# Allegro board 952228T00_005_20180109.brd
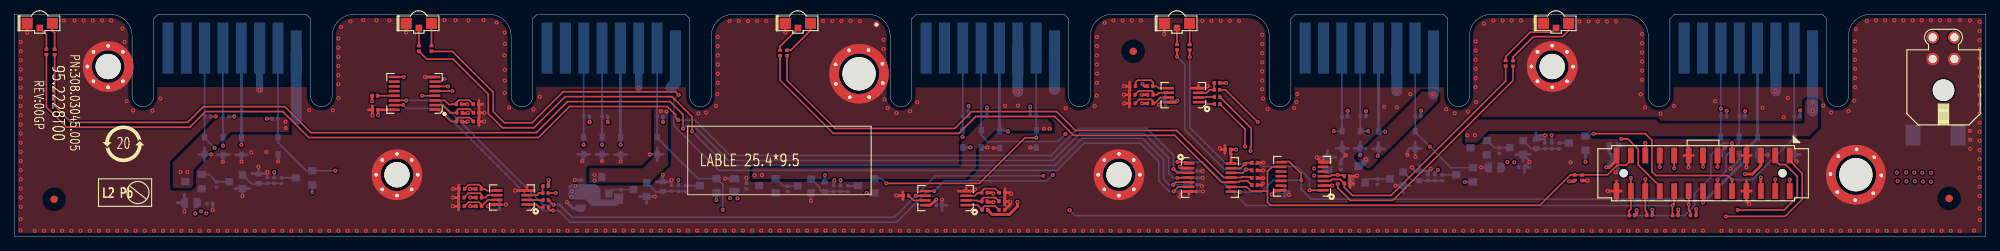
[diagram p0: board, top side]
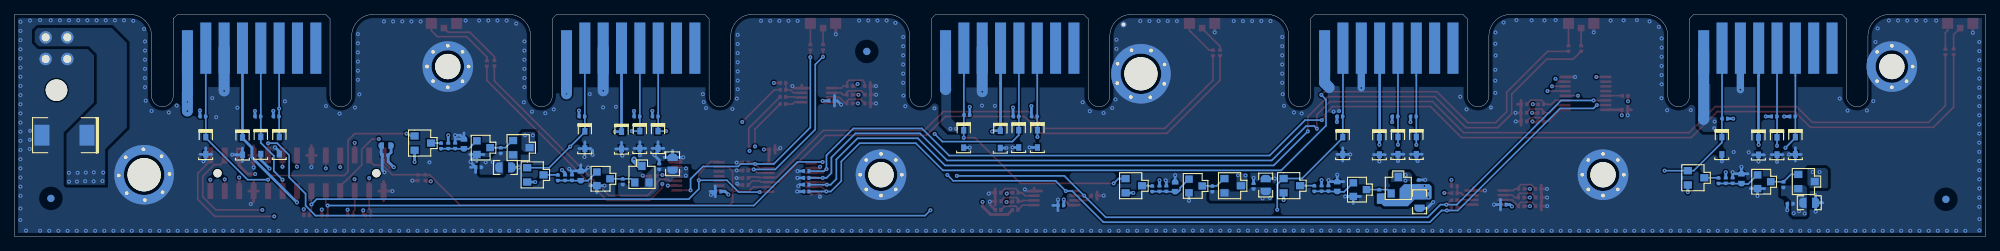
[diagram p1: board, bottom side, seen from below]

Outline 273 x 30.8 mm; copper layers: TOP, G02, T03, P04, G05, BOTTOM. Coordinates in mm from the lower left corner of the outline.
Outline path: 0,30.8 0,0 273,0 273,30.8 257.01,30.8 arc(254.89,29.92) 254.01,27.8 254.01,19.5 arc(252.51,18) 251.01,19.5 251.01,30.2 250.41,30.8 229.89,30.8 229.29,30.2 229.29,19.5 arc(227.79,18) 226.29,19.5 226.29,27.8 arc(225.41,29.92) 223.29,30.8 204.51,30.8 arc(202.39,29.92) 201.51,27.8 201.51,19.5 arc(200.01,18) 198.51,19.5 198.51,30.2 197.91,30.8 177.39,30.8 176.79,30.2 176.79,19.5 arc(175.29,18) 173.79,19.5 173.79,27.8 arc(172.91,29.92) 170.79,30.8 152.01,30.8 arc(149.89,29.92) 149.01,27.8 149.01,19.5 arc(147.51,18) 146.01,19.5 146.01,30.2 145.41,30.8 124.89,30.8 124.29,30.2 124.29,19.5 arc(122.79,18) 121.29,19.5 121.29,27.8 arc(120.41,29.92) 118.29,30.8 99.51,30.8 arc(97.39,29.92) 96.51,27.8 96.51,19.5 arc(95.01,18) 93.51,19.5 93.51,30.2 92.91,30.8 72.39,30.8 71.79,30.2 71.79,19.5 arc(70.29,18) 68.79,19.5 68.79,27.8 arc(67.91,29.92) 65.79,30.8 47.01,30.8 arc(44.89,29.92) 44.01,27.8 44.01,19.5 arc(42.51,18) 41.01,19.5 41.01,30.2 40.41,30.8 19.89,30.8 19.29,30.2 19.29,19.5 arc(17.79,18) 16.29,19.5 16.29,27.8 arc(15.41,29.92) 13.29,30.8 0,30.8

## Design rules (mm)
net group I2C: nets I2C0_HWM_SCL I2C0_HWM_SDA
net group LED_FAN: nets LED_FAN_SCL LED_FAN_SDA
net group FAN-LED-GY: nets FAN1_LED_G FAN1_LED_Y FAN2_LED_G FAN2_LED_Y FAN3_LED_G FAN3_LED_Y FAN4_LED_G FAN4_LED_Y FAN5_LED_G FAN5_LED_Y
net group FAN-PRSNT: nets FAN1_PRSNT_N FAN2_PRSNT_N FAN3_PRSNT_N FAN4_PRSNT_N FAN5_PRSNT_N
net group FAN_DIR: nets FAN1_DIR# FAN2_DIR# FAN3_DIR# FAN4_DIR# FAN5_DIR#
net group FAN_TACH: nets FAN1_TACH_IN FAN2_TACH_IN FAN3_TACH_IN FAN4_TACH_IN FAN5_TACH_IN
net group POWER: nets FAN1_PWM_CTRL FAN2_PWM_CTRL FAN3_PWM_CTRL FAN4_PWM_CTRL FAN4_PWR FAN5_PWM_CTRL

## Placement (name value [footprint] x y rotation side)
C1  10uF  [C-0805-H1_35]  24.42 4.68 270 bottom
C2  100nF  [C-0402S0]  27.06 4.56 90 bottom
C3  1uF  [C-0603S0]  33.81 8.03 180 bottom
C4  10uF  [C-0805-H1_35]  99.7 7.15 180 bottom
C5  100nF  [C-0402S0]  183.7 9.71 180 bottom
C6  1uF  [C-0603S0]  89.79 6.93 180 bottom
C7  10uF  [C-0805-H1_35]  181.85 10.09 180 bottom
C8  100nF  [C-0402S0]  101.38 7 180 bottom
C9  1uF  [C-0603S0]  112.25 6.91 180 bottom
C10  10uF  [C-0805-H1_35]  78.39 4.81 0 bottom
C11  100nF  [C-0402S0]  208.72 9.61 90 bottom
C12  1uF  [C-0603S0]  194.57 8.43 180 bottom
C13  10uF  [C-0805-H1_35]  205.01 9.59 270 bottom
C14  100nF  [C-0402S0]  78.52 7.45 180 bottom
C15  1uF  [C-0603S0]  210.75 12.85 180 bottom
C16  68uF  [C-S7_3X4_3B]  266.07 14.06 90 bottom
C17  10uF  [C-0603S0]  221.52 12.61 90 bottom
C18  100nF  [C-0402S0]  221.65 11.26 90 bottom
C19  100nF  [C-0402S0]  66.77 4.43 90 bottom
C20  100nF  [C-0402S0]  159.82 18.83 270 bottom
C21  100nF  [C-0402S0]  128.07 4.33 90 bottom
C22  100nF  [C-0402S0]  168.05 12.08 270 top
C23  1nF  [C-0402S0]  163.33 9.08 90 bottom
C24  1nF  [C-0402S0]  163.33 8.14 90 bottom
C25  1nF  [C-0402S0]  163.33 7.19 90 bottom
C26  1nF  [C-0402S0]  163.33 6.25 90 bottom
C27  1nF  [C-0402S0]  171.76 7.15 270 top
C28  1nF  [C-0402S0]  171.76 8.11 270 top
C29  1nF  [C-0402S0]  171.76 9.18 270 top
C30  1nF  [C-0402S0]  171.76 10.25 270 top
C31  100nF  [C-0402S0]  175.53 6.25 270 bottom
C32  1nF  [C-0402S0]  184.59 7.35 270 top
C33  1nF  [C-0402S0]  184.56 8.37 270 top
C34  100nF  [C-0402S0]  49.97 17.58 90 top
D1  SP4020-01FTG  [SOD-323H1_1]  31.45 12.54 0 bottom
D2  SP4020-01FTG  [SOD-323H1_1]  36.52 12.59 0 bottom
D3  SP4020-01FTG  [SOD-323H1_1]  28.88 12.56 0 bottom
D4  SP4020-01FTG  [SOD-323H1_1]  83.95 12.56 0 bottom
D5  SP4020-01FTG  [SOD-323H1_1]  89.03 12.59 0 bottom
D6  SP4020-01FTG  [SOD-323H1_1]  81.38 12.61 0 bottom
D7  SP4020-01FTG  [SOD-323H1_1]  136.45 13.48 0 bottom
D8  SP4020-01FTG  [SOD-323H1_1]  141.53 13.53 0 bottom
D9  SP4020-01FTG  [SOD-323H1_1]  133.91 13.55 0 bottom
D10  SP4020-01FTG  [SOD-323H1_1]  188.92 13.35 0 bottom
D11  SP4020-01FTG  [SOD-323H1_1]  194 13.4 0 bottom
D12  SP4020-01FTG  [SOD-323H1_1]  186.38 13.43 0 bottom
D13  SP4020-01FTG  [SOD-323H1_1]  241.42 12.54 0 bottom
D14  SP4020-01FTG  [SOD-323H1_1]  246.5 12.59 0 bottom
D15  SP4020-01FTG  [SOD-323H1_1]  238.88 12.63 0 bottom
D16  SP4020-01FTG  [SOD-323H1_1]  26.34 12.59 0 bottom
D17  SP4020-01FTG  [SOD-323H1_1]  78.84 12.61 0 bottom
D18  SP4020-01FTG  [SOD-323H1_1]  131.32 13.55 0 bottom
D19  SP4020-01FTG  [SOD-323H1_1]  183.87 13.43 0 bottom
D20  SP4020-01FTG  [SOD-323H1_1]  236.32 12.61 0 bottom
D21  12-22A/Y2G6C-B30/2C  [LD-12-22H1S1]  3.51 29.56 270 top
D22  12-22A/Y2G6C-B30/2C  [LD-12-22H1S1]  56.01 29.56 270 top
D23  12-22A/Y2G6C-B30/2C  [LD-12-22H1S1]  108.51 29.56 270 top
D24  12-22A/Y2G6C-B30/2C  [LD-12-22H1S1]  161.01 29.56 270 top
D25  12-22A/Y2G6C-B30/2C  [LD-12-22H1S1]  213.51 29.56 270 top
FD*  -  [unnamed#2]  5.49 5.17 0 top
FD*#2  -  [unnamed#2]  154.95 25.69 0 top
FD*#3  -  [unnamed#2]  267.95 5.29 0 top
FD*#4  -  [unnamed#2]  154.95 25.66 180 bottom
FD*#5  -  [unnamed#2]  5.49 5.17 180 bottom
FD*#6  -  [unnamed#2]  267.95 5.29 180 bottom
H1  Hole-3.5/7.0mm  [GMTH138R276]  212.98 23.57 0 top
H2  Hole-4.6/8.0mm  [GMTH181R325S0]  255.04 8.57 0 top
H3  Hole-3.5/7.0mm  [GMTH138R276]  52.98 8.57 0 top
H4  Hole-3.5/7.0mm  [GMTH138R276]  152.98 8.57 0 top
H5  Hole-4.6/8.0mm  [GMTH181R325S0]  116.98 22.57 25 top
H6  Hole-3.5/7.0mm  [GMTH138R276#2]  12.98 23.57 0 top
J1  FAN CONN  [CN-S8X1-2_54-FPC]  30.15 24.82 90 bottom
J2  FAN CONN  [CN-S8X1-2_54-FPC]  82.65 24.82 90 bottom
J3  FAN CONN  [CN-S8X1-2_54-FPC]  135.15 24.82 90 bottom
J4  FAN CONN  [CN-S8X1-2_54-FPC]  187.65 24.82 90 bottom
J5  FAN CONN  [CN-S8X1-2_54-FPC]  240.15 24.82 90 bottom
J6  HS5513V-R  [CN-S13X2-2HD]  233.87 8.78 90 top
J7  HM4002E-LH  [CN-D2X2-3BRTS0]  267.18 20.69 0 top
NOREF  -  []  15.1 12.86 0 top
NOREF#2  -  []  -72.65 -339.14 0 top
NOREF#3  -  []  0 30.8 0 top
NOREF#4  -  []  151.85 -209.5 0 top
NOREF#5  -  []  11.39 4.2 0 top
NOREF#6  -  []  0 0 90 top
NOREF#7  -  []  -208.37 -462.07 0 top
Q1  AP2323GN-HF  [SOT-23D]  24.8 7.63 0 bottom
Q2  AP2323GN-HF  [SOT-23D]  40.1 8.15 0 bottom
Q3  AP2323GN-HF  [SOT-23D]  81.34 7.12 270 bottom
Q4  AP2323GN-HF  [SOT-23D]  96.08 7.06 0 bottom
Q5  AP2323GN-HF  [SOT-23D]  104.27 7.05 0 bottom
Q6  AP2323GN-HF  [SOT-23D]  117.97 7.05 0 bottom
Q7  AP2323GN-HF  [SOT-23D]  186.09 8.65 270 bottom
Q8  AP2323GN-HF  [SOT-23D]  200.85 8.55 0 bottom
Q9  AP2323GN-HF  [SOT-23D]  202.8 12.33 0 bottom
Q10  AP2323GN-HF  [SOT-23D]  216.44 12.96 0 bottom
R1  10Kohm  [R-0402S0]  28 7.2 180 bottom
R2  10Kohm  [R-0402S0]  35.98 7.77 0 bottom
R3  10Kohm  [R-0402S0]  36.98 7.75 180 bottom
R4  100Kohm  [R-0402S0]  35.03 7.77 180 bottom
R5  1Kohm  [R-0402S0]  36.1 16.35 270 bottom
R6  1Kohm  [R-0402S0]  29.29 16.65 90 bottom
R7  10Kohm  [R-0402S0]  83.98 6.11 180 bottom
R8  10Kohm  [R-0402S0]  91.96 6.68 0 bottom
R9  10Kohm  [R-0402S0]  92.97 6.65 180 bottom
R10  100Kohm  [R-0402S0]  91.01 6.68 180 bottom
R11  1Kohm  [R-0402S0]  89.43 16.65 90 bottom
R12  1Kohm  [R-0402S0]  81.79 16.65 90 bottom
R13  10Kohm  [R-0402S0]  107.09 6.61 180 bottom
R14  10Kohm  [R-0402S0]  114.41 6.65 0 bottom
R15  10Kohm  [R-0402S0]  115.42 6.63 180 bottom
R16  100Kohm  [R-0402S0]  113.46 6.65 180 bottom
R17  1Kohm  [R-0402S0]  141.1 16.87 270 bottom
R18  1Kohm  [R-0402S0]  134.29 16.65 90 bottom
R19  10Kohm  [R-0402S0]  188.76 7.6 180 bottom
R20  10Kohm  [R-0402S0]  196.74 8.17 0 bottom
R21  10Kohm  [R-0402S0]  197.74 8.15 180 bottom
R22  100Kohm  [R-0402S0]  195.79 8.18 180 bottom
R23  1Kohm  [R-0402S0]  194.41 16.65 90 bottom
R24  1Kohm  [R-0402S0]  186.79 16.65 90 bottom
R25  10Kohm  [R-0402S0]  205.65 11.92 180 bottom
R26  10Kohm  [R-0402S0]  212.92 12.59 0 bottom
R27  10Kohm  [R-0402S0]  213.92 12.57 180 bottom
R28  100Kohm  [R-0402S0]  211.97 12.6 180 bottom
R29  1Kohm  [R-0402S0]  246.91 16.65 90 bottom
R30  1Kohm  [R-0402S0]  239.29 16.65 90 bottom
R31  4.7K  [R-0402S0]  73.57 7 270 top
R32  4.7K  [R-0402S0]  64.31 4.22 270 top
R33  0ohm  [R-0402S0]  73.56 6.02 270 top
R34  4.7K  [R-0402S0]  64.31 5.41 270 top
R35  4.7K  [R-0402S0]  64.28 6.61 270 top
R36  0ohm  [R-0402S0]  73.58 4.05 90 top
R37  4.7K  [R-0402S0]  61.92 4.22 270 top
R38  4.7K  [R-0402S0]  61.9 5.41 270 top
R39  0ohm  [R-0402S0]  73.58 5.04 90 top
R40  4.7K  [R-0402S0]  61.95 6.61 270 top
R41  4.7Kohm  [R-0402S0]  226.45 2.96 90 top
R42  4.7Kohm  [R-0402S0]  224.04 2.93 90 top
R43  4.7K  [R-0402S0]  166.56 21.3 270 top
R44  4.7K  [R-0402S0]  157.33 18.47 270 top
R45  4.7K  [R-0402S0]  157.33 19.66 270 top
R46  4.7K  [R-0402S0]  157.3 20.86 270 top
R47  0ohm  [R-0402S0]  166.55 20.35 270 top
R48  0ohm  [R-0402S0]  166.57 18.38 90 top
R49  4.7K  [R-0402S0]  154.84 18.47 270 top
R50  4.7K  [R-0402S0]  154.81 19.66 270 top
R51  0ohm  [R-0402S0]  166.57 19.37 90 top
R52  4.7K  [R-0402S0]  154.86 20.86 270 top
R53  4.7Kohm  [R-0402S0]  134.35 6.08 90 top
R54  4.7Kohm  [R-0402S0]  134.36 4.89 90 top
R55  4.7Kohm  [R-0402S0]  134.41 3.69 90 top
R56  4.7Kohm  [R-0402S0]  136.78 6.09 270 top
R57  4.7Kohm  [R-0402S0]  136.75 4.89 270 top
R58  4.7Kohm  [R-0402S0]  136.75 3.69 270 top
R59  200ohm  [R-0402S0]  123.46 5.68 90 top
R60  4.7Kohm  [R-0402S0]  232.52 2.96 90 top
R61  4.7Kohm  [R-0402S0]  230.03 2.93 90 top
R62  4.7Kohm  [R-0402S0]  216.09 8.16 0 top
R63  4.7Kohm  [R-0402S0]  217.13 8.16 180 top
R64  4.7Kohm  [R-0402S0]  49.93 19.53 270 top
R65  4.7Kohm  [R-0402S0]  61.61 15.97 90 top
R66  4.7Kohm  [R-0402S0]  61.64 17.16 90 top
R67  4.7Kohm  [R-0402S0]  61.56 18.35 90 top
R68  4.7Kohm  [R-0402S0]  63.93 15.96 270 top
R69  4.7Kohm  [R-0402S0]  63.95 17.16 270 top
R70  150ohm  [R-0402S0]  4.42 25.62 180 top
R71  150ohm  [R-0402S0]  5.57 25.6 180 top
R72  150ohm  [R-0402S0]  56.01 26.08 180 top
R73  150ohm  [R-0402S0]  57.76 26.08 180 top
R74  150ohm  [R-0402S0]  106.02 25.47 180 top
R75  150ohm  [R-0402S0]  107.01 25.45 180 top
R76  150ohm  [R-0402S0]  161.01 26.26 180 top
R77  150ohm  [R-0402S0]  162.76 26.24 180 top
R78  150ohm  [R-0402S0]  206.53 24.03 180 top
R79  150ohm  [R-0402S0]  207.57 24.01 180 top
R80  4.7Kohm  [R-0402S0]  63.93 18.35 270 top
R81  1Kohm  [R-0402S0]  26.74 16.65 90 bottom
R82  1Kohm  [R-0402S0]  79.25 16.65 90 bottom
R83  1Kohm  [R-0402S0]  131.74 16.65 90 bottom
R84  1Kohm  [R-0402S0]  184.24 16.65 90 bottom
R85  1Kohm  [R-0402S0]  236.74 16.65 90 bottom
U1  2N7002  [SOT-23BH1_11]  30.67 7.6 0 bottom
U2  2N7002  [SOT-23BH1_11]  86.65 6.51 0 bottom
U3  2N7002  [SOT-23BH1_11]  109.41 7.02 0 bottom
U4  2N7002  [SOT-23BH1_11]  191.42 8.01 0 bottom
U5  2N7002  [SOT-23BH1_11]  208.03 12.33 0 bottom
U6  TMP75AIDGKR  [MSOP-8]  68.9 5.41 0 top
U7  TMP75AIDGKR  [MSOP-8]  161.89 19.61 0 top
U8  M24128-BRDW6TP  [MSOP-8A]  128.96 5.34 0 top
U9  MC74HC164ADTR2G  [SSOP-14S0]  165.59 8.19 180 top
U10  MC74HC164ADTR2G  [SSOP-14S0]  178.34 8.37 0 top
U11  TCA9554PWR  [SSOP-16C]  55.41 19.85 0 top

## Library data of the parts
C1-C15 C17-C34 = CAP
C16 = CAP-TAN
D1-D20 = DIODE ZENER
D21-D25 = LED-YG-3
H1-H6 = Hole-MTG-8VIA
J1-J5 = FAN CONN_3
J6 = CON13X2
J7 = CON2X2
Q1-Q10 = PFET-3P-GSD
R1-R85 = RES
U1-U5 = NFET-3P-GSD
U6 U7 = ADT75ARZ
U8 = M24C02
U9 U10 = SN74HC164D_0
U11 = PCA9557PW_1

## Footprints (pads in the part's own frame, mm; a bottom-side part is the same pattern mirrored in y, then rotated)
C-0402S0
  custom 0.127x0.127 smd: 1(0,-0.406) 2(0,0.406)
C-0603S0
  custom 0.191x0.191 smd: 1(0,-0.686) 2(0,0.686)
C-0805-H1_35
  custom 0.254x0.254 smd: 1(0,-0.889) 2(0,0.889)
C-S7_3X4_3B
  rect 2.896x2.083 smd: 1(0,-3.123) 2(0,3.123)
CN-D2X2-3BRTS0
  round 2.997 hole 2.997 unplated: (0,-0.391)
  round 1.727 hole 1.118: 1(1.501,3.929) 2(-1.499,3.929) 3(1.501,6.929) 4(-1.499,6.929)
CN-S8X1-2_54-FPC
  rect 6.045x1.524 smd: 1(0.77,8.89)
  rect 7.112x1.524 smd: 2(1.306,6.35) 3(1.306,3.81) 4(1.306,1.27) 5(1.306,-1.27) 6(1.306,-3.81) 7(1.306,-6.35) 8(1.306,-8.89)
CN-S13X2-2HD
  round 1.143 hole 1.143 unplated: (0,11.001) (0,-11.001)
  rect 2.184x0.813 smd: 1(2.471,-11.999) 2(-2.471,-11.999) 3(2.471,-10) 4(-2.471,-10) 5(2.471,-8.001) 6(-2.471,-8.001) 7(2.471,-5.999) 8(-2.471,-5.999) 9(2.471,-4) 10(-2.471,-4) 11(2.471,-1.999) 12(-2.471,-1.999) 13(2.471,0) 14(-2.471,0) 15(2.471,1.999) 16(-2.471,1.999) 17(2.471,4) 18(-2.471,4) 19(2.471,5.999) 20(-2.471,5.999) 21(2.471,8.001) 22(-2.471,8.001) 23(2.471,10) 24(-2.471,10) 25(2.471,11.999) 26(-2.471,11.999)
GMTH138R276
  round 3.505 hole 3.505 unplated: (0,0)
  round 0.813 hole 0.508: 1(2.883,0) 2(2.039,2.039) 3(0,2.883) 4(-2.039,2.039) 5(-2.883,0) 6(-2.039,-2.039) 7(0,-2.883) 8(2.039,-2.039)
GMTH138R276#2
  round 3.505 hole 3.505 unplated: (0,0)
  round 0.813 hole 0.508: 1(106.41,5.829) 2(2.039,2.039) 3(0,2.883) 4(-2.039,2.039) 5(-2.883,0) 6(-2.039,-2.039) 7(0,-2.883) 8(2.039,-2.039)
GMTH181R325S0
  round 4.597 hole 4.597 unplated: (0,0)
  round 0.813 hole 0.508: 1(0.102,3.516) 2(-2.415,2.558) 3(-3.516,0.102) 4(-2.558,-2.415) 5(-0.102,-3.516) 6(2.415,-2.558) 7(3.516,-0.102) 8(2.558,2.415)
LD-12-22H1S1
  rect 0.914x0.914 smd: 1(0.65,0)
  rect 1.524x1.524 smd: 2(0,1.75) 3(0,-1.75)
MSOP-8
  rect 1.524x0.356 smd: 1(2.07,-0.975) 2(2.07,-0.325) 3(2.07,0.325) 4(2.07,0.975) 5(-2.07,0.975) 6(-2.07,0.325) 7(-2.07,-0.325) 8(-2.07,-0.975)
MSOP-8A
  rect 1.524x0.356 smd: 1(2.819,-0.975) 2(2.819,-0.325) 3(2.819,0.325) 4(2.819,0.975) 5(-2.819,0.975) 6(-2.819,0.325) 7(-2.819,-0.325) 8(-2.819,-0.975)
R-0402S0
  custom 0.127x0.127 smd: 1(0,-0.406) 2(0,0.406)
SOD-323H1_1
  rect 0.711x0.914 smd: 1(0,1.199) 2(0,-1.199)
SOT-23BH1_11
  rect 1.067x1.016 smd: 1(0.919,-0.95) 2(0.919,0.95) 3(-0.919,0)
SOT-23D
  rect 1.143x1.016 smd: 1(1.143,-0.991) 2(1.143,0.991) 3(-1.143,0)
SSOP-14S0
  rect 1.524x0.356 smd: 1(2.918,-1.951) 2(2.918,-1.3) 3(2.918,-0.65) 4(2.918,0) 5(2.918,0.65) 6(2.918,1.3) 7(2.918,1.951) 8(-2.918,1.951) 9(-2.918,1.3) 10(-2.918,0.65) 11(-2.918,0) 12(-2.918,-0.65) 13(-2.918,-1.3) 14(-2.918,-1.951)
SSOP-16C
  rect 1.524x0.356 smd: 1(2.819,-2.276) 2(2.819,-1.626) 3(2.819,-0.975) 4(2.819,-0.325) 5(2.819,0.325) 6(2.819,0.975) 7(2.819,1.626) 8(2.819,2.276) 9(-2.819,2.276) 10(-2.819,1.626) 11(-2.819,0.975) 12(-2.819,0.325) 13(-2.819,-0.325) 14(-2.819,-0.975) 15(-2.819,-1.626) 16(-2.819,-2.276)
unnamed#2
  round 1.016 smd: 1(0,0)

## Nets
FAN1_DIR#: D16.2(C) J1.6(GND_INLET) R81.1 U11.4(P0)
FAN1_LED_G: C24.1 R71.2 U9.4(QB)
FAN1_LED_Y: C23.1 R70.2 U9.3(QA)
FAN1_PRSNT_N: D2.2(C) J1.2(PRSNT_N) J6.1 Q2.1(G) R5.1
FAN1_PWM_CTRL: D1.2(C) J1.4(PWM_OUTLET) J6.5
FAN1_PWR: J1.1(P12V) Q1.3(D)
FAN1_PWR_ON: C3.1 R2.2 R3.1 R4.1 U1.1(G)
FAN1_TACH_IN: D3.2(C) J1.5(TACH_OUTLET) J6.3 R6.1
FAN2_DIR#: D17.2(C) J2.6(GND_INLET) R82.1 U11.5(P1)
FAN2_LED_G: C26.1 R73.2 U9.6(QD)
FAN2_LED_Y: C25.1 R72.2 U9.5(QC)
FAN2_PRSNT_N: D5.2(C) J2.2(PRSNT_N) J6.9 Q4.1(G) R11.1
FAN2_PWM_CTRL: D4.2(C) J2.4(PWM_OUTLET) J6.13
FAN2_PWR: J2.1(P12V) Q3.3(D)
FAN2_PWR_ON: C6.1 R8.2 R9.1 R10.1 U2.1(G)
FAN2_TACH_IN: D6.2(C) J2.5(TACH_OUTLET) J6.11 R12.1
FAN3_DIR#: D18.2(C) J3.6(GND_INLET) R83.1 U11.6(P2)
FAN3_LED_G: C28.1 R75.2 U9.11(QF)
FAN3_LED_Y: C27.1 R74.2 U9.10(QE)
FAN3_PRSNT_N: D8.2(C) J3.2(PRSNT_N) J6.17 Q6.1(G) R17.1
FAN3_PWM_CTRL: D7.2(C) J3.4(PWM_OUTLET) J6.21
FAN3_PWR: J3.1(P12V) Q5.3(D)
FAN3_PWR_ON: C9.1 R14.2 R15.1 R16.1 U3.1(G)
FAN3_TACH_IN: D9.2(C) J3.5(TACH_OUTLET) J6.19 R18.1
FAN4_DIR#: D19.2(C) J4.6(GND_INLET) R84.1 U11.7(P3)
FAN4_LED_G: C30.1 R77.2 U9.13(QH) U10.1(A)
FAN4_LED_Y: C29.1 R76.2 U9.12(QG)
FAN4_PRSNT_N: D11.2(C) J4.2(PRSNT_N) J6.2 Q8.1(G) R23.1
FAN4_PWM_CTRL: D10.2(C) J4.4(PWM_OUTLET) J6.6
FAN4_PWR: J4.1(P12V) Q7.3(D)
FAN4_PWR_ON: C12.1 R20.2 R21.1 R22.1 U4.1(G)
FAN4_TACH_IN: D12.2(C) J4.5(TACH_OUTLET) J6.4 R24.1
FAN5_DIR#: D20.2(C) J5.6(GND_INLET) R85.1 U11.9(P4)
FAN5_LED_G: C33.1 R79.2 U10.4(QB)
FAN5_LED_Y: C32.1 R78.2 U10.3(QA)
FAN5_PRSNT_N: D14.2(C) J5.2(PRSNT_N) J6.10 Q10.1(G) R29.1
FAN5_PWM_CTRL: D13.2(C) J5.4(PWM_OUTLET) J6.14
FAN5_PWR: J5.1(P12V) Q9.3(D)
FAN5_PWR_ON: C15.1 R26.2 R27.1 R28.1 U5.1(G)
FAN5_TACH_IN: D15.2(C) J5.5(TACH_OUTLET) J6.12 R30.1
FAN_GND: C1.2 C2.2 C3.2 C4.2 C5.2 C6.2 C7.2 C8.2 C9.2 C10.2 C11.2 C12.2 C13.2 C14.2 C15.2 C16.2 C17.2 C18.2 C19.2 C20.2 C21.2 C22.1 C23.2 C24.2 C25.2 C26.2 C27.2 C28.2 C29.2 C30.2 C31.1 C32.2 C33.2 C34.2 D1.1(A) D2.1(A) D3.1(A) D4.1(A) D5.1(A) D6.1(A) D7.1(A) D8.1(A) D9.1(A) D10.1(A) D11.1(A) D12.1(A) D13.1(A) D14.1(A) D15.1(A) D16.1(A) D17.1(A) D18.1(A) D19.1(A) D20.1(A) D21.3 D22.3 D23.3 D24.3 D25.3 H1.1(GND1) H1.2(GND2) H1.3(GND3) H1.4(GND4) H1.5(GND5) H1.6(GND6) H1.7(GND7) H1.8(GND8) H2.1(GND1) H2.2(GND2) H2.3(GND3) H2.4(GND4) H2.5(GND5) H2.6(GND6) H2.7(GND7) H2.8(GND8) H3.1(GND1) H3.2(GND2) H3.3(GND3) H3.4(GND4) H3.5(GND5) H3.6(GND6) H3.7(GND7) H3.8(GND8) H4.1(GND1) H4.2(GND2) H4.3(GND3) H4.4(GND4) H4.5(GND5) H4.6(GND6) H4.7(GND7) H4.8(GND8) H5.1(GND1) H5.2(GND2) H5.3(GND3) H5.4(GND4) H5.5(GND5) H5.6(GND6) H5.7(GND7) H5.8(GND8) H6.1(GND1) H6.2(GND2) H6.3(GND3) H6.4(GND4) H6.5(GND5) H6.6(GND6) H6.7(GND7) H6.8(GND8) J1.3(GND_OUTLET) J2.3(GND_OUTLET) J3.3(GND_OUTLET) J4.3(GND_OUTLET) J5.3(GND_OUTLET) J6.7 J6.8 J6.15 J6.26 J7.1 J7.2 R4.2 R10.2 R16.2 R22.2 R28.2 R37.1 R38.1 R40.1 R49.1 R50.1 R52.1 R56.2 R57.2 R58.2 R59.2 R63.2 R68.2 R69.2 R80.2 U1.2(S) U2.2(S) U3.2(S) U4.2(S) U5.2(S) U6.4(GND) U7.4(GND) U8.4(VSS) U9.7(GND) U10.7(GND) U11.8(GND)
FAN_P3V3: C17.1 C18.1 C19.1 C20.1 C21.1 C22.2 C31.2 C34.1 J6.25 Q2.2(S) Q4.2(S) Q6.2(S) Q8.2(S) Q10.2(S) R2.1 R5.2 R6.2 R8.1 R11.2 R12.2 R14.1 R17.2 R18.2 R20.1 R23.2 R24.2 R26.1 R29.2 R30.2 R31.2 R32.1 R34.1 R35.1 R41.1 R42.1 R43.2 R44.1 R45.1 R46.1 R53.1 R54.1 R55.1 R60.1 R61.1 R62.1 R64.1 R65.1 R66.1 R67.1 R81.2 R82.2 R83.2 R84.2 R85.2 U6.8(VDD) U7.8(VDD) U8.8(VCC) U9.2(B) U9.14(VCC) U10.2(B) U10.14(VCC) U11.16(VCC)
FAN_P12V: C1.1 C2.1 C4.1 C5.1 C7.1 C8.1 C10.1 C11.1 C13.1 C14.1 C16.1 J7.3 J7.4 Q1.2(S) Q3.2(S) Q5.2(S) Q7.2(S) Q9.2(S) R1.1 R7.1 R13.1 R19.1 R25.1
I2C0_HWM_SCL: J6.22 R39.1 R41.2 R51.1 U8.6(SCL) U11.14(SCL)
I2C0_HWM_SDA: J6.24 R36.1 R42.2 R48.1 U8.5(SDA) U11.15(SDA)
LED_FAN_CLR_N: J6.23 R62.2 R63.1 U9.9(CLR#) U10.9(CLR#)
LED_FAN_SCL: J6.16 R60.2 U9.8(CLK) U10.8(CLK)
LED_FAN_SDA: J6.18 R61.2 U9.1(A)
TEMP_ALERT: J6.20 R33.2 R47.2
N02942: Q1.1(G) R1.2 U1.3(D)
N03390: Q2.3(D) R3.2
N11321: Q3.1(G) R7.2 U2.3(D)
N11737: Q4.3(D) R9.2
N13765: Q5.1(G) R13.2 U3.3(D)
N14181: Q6.3(D) R15.2
N14871: Q8.3(D) R21.2
N17617712: Q7.1(G) R19.2 U4.3(D)
N32077972: R34.2 R38.2 U6.6(A1)
N32077983: R32.2 R37.2 U6.7(A0)
N32078033: R35.2 R40.2 U6.5(A2)
N32081443: R31.1 R33.1 U6.3(OS/ALERT)
N32081820: R44.2 R49.2 U7.7(A0)
N32081822: R45.2 R50.2 U7.6(A1)
N32081881: R46.2 R52.2 U7.5(A2)
N32081935: R51.2 U7.2(SCL)
N32081937: R48.2 U7.1(SDA)
N32081960: R43.1 R47.1 U7.3(OS/ALERT)
N48201953: Q9.1(G) R25.2 U5.3(D)
N48202027: Q10.3(D) R27.2
N48243003: R36.2 U6.1(SDA)
N48243020: R39.2 U6.2(SCL)
N48490379: D21.2 R71.1
N48490381: D21.1 R70.1
N48490814: D22.1 R72.1
N48490816: D22.2 R73.1
N48491189: D23.1 R74.1
N48491191: D23.2 R75.1
N48491244: D24.1 R76.1
N48491268: D24.2 R77.1
N48491368: D25.1 R78.1
N48491396: D25.2 R79.1
N48524136: R59.1 U8.7(W\C\)
N48524194: R55.2 R58.1 U8.1(E0)
N48524219: R54.2 R57.1 U8.2(E1)
N48524300: R53.2 R56.1 U8.3(E2)
N48567665: R65.2 R68.1 U11.1(A0)
N48567697: R66.2 R69.1 U11.2(A1)
N48567724: R67.2 R80.1 U11.3(A2)
N48567766: R64.2 U11.13(I\N\T\)

Pads without a net: FD* 1; FD*#2 1; FD*#3 1; FD*#4 1; FD*#5 1; FD*#6 1; J1 7 8; J2 7 8; J3 7 8; J4 7 8; J5 7 8; U10 5 6 10 11 12 13; U11 10 11 12

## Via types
v1: diameter 0.559, hole 0.203, TOP to BOTTOM, 115 vias
v2: diameter 0.559, hole 0.254, TOP to BOTTOM, 563 vias

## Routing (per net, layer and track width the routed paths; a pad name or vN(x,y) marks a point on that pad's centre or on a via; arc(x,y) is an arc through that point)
FAN1_DIR#: length 48.2
  TOP w0.229: v1(56.45,19.53) U11.4
  T03 w0.229: v1(27.72,12.3) 27.72,12.75 29.38,14.41 51.33,14.41 v1(56.45,19.53)
  BOTTOM w0.229: J1.6 26.34,22.32 26.34,22.32 R81.1 D16.2 26.34,13.69 v1(27.72,12.3)
FAN1_LED_G: length 181.4
  TOP w0.229: U9.4 161.66,8.19 161.61,8.14 v1(161.04,8.14) ; v1(92.61,14.96) 92.61,16.91 90.8,18.71 76.59,18.71 72.29,14.41 41.05,14.41 37.45,18.02 26.17,18.02 23.99,15.83 7.88,15.83 5.57,18.15 R71.2
  BOTTOM w0.229: v1(92.61,14.96) 92.98,15.33 94.09,15.33 98.87,10.55 143.83,10.55 147.59,14.31 156.52,14.31 159.85,10.98 159.85,8.81 160.52,8.14 v1(161.04,8.14) 161.69,8.14 161.69,8.14 C24.1
FAN1_LED_Y: length 181.6
  TOP w0.229: v1(160.54,9.36) 161.05,8.84 U9.3 ; v1(91.92,16.15) 91.55,16.52 91.55,16.9 90.43,18.03 76.88,18.03 72.58,13.73 40.77,13.73 37.16,17.33 26.45,17.33 24.27,15.15 7.22,15.15 4.42,17.95 R70.2
  BOTTOM w0.229: v1(91.92,16.15) 94.24,16.15 99.15,11.24 143.54,11.24 147.3,15 156.8,15 160.54,11.26 v1(160.54,9.36) 160.61,9.36 160.89,9.08 C23.1
FAN1_PRSNT_N: length 236.2
  TOP w0.229: J6.1 245.87,10.57 246.45,9.99 246.45,9.91 247.61,8.76 247.61,5.17 245.24,2.8 v1(237.02,2.8)
  T03 w0.229: v1(237.02,2.8) 236.85,2.96 50.63,2.96 v1(44.46,9.14)
  BOTTOM w0.229: v1(44.46,9.14) Q2.1 40.42,9.14 36.52,13.03 D2.2 36.52,14.49 36.51,14.5 R5.1 36.5,16.36 J1.2
FAN1_PWM_CTRL: length 236.8
  TOP w0.381: J6.5 241.88,9.84 240.71,8.67 v2(239.67,8.67)
  T03 w0.381: v2(239.67,8.67) 239.67,2.81 238.37,1.52 49.89,1.52 38.68,12.72 v2(31.43,12.72)
  BOTTOM w0.381: v2(31.43,12.72) 31.45,12.75 D1.2 31.45,22.22 31.42,22.25 J1.4
FAN1_PWR: length 9.3
  BOTTOM w1.524: J1.1 39.04,16.28 39.07,16.26
  vias: v1(37.53,15.94) v1(37.58,15.03) v2(22.99,8.95) v2(23.93,8.95)
FAN1_PWR_ON: length 6
  BOTTOM w0.229: U1.1 31.61,8.55 32.88,7.29 33.76,7.29 C3.1 35,7.34 R4.1 35.97,7.37 R2.2 36.96,7.36 R3.1
FAN1_TACH_IN: length 245.9
  TOP w0.229: v1(238.67,3.69) 245.1,3.69 246.92,5.52 246.92,8.36 245.3,9.99 244.45,9.99 243.87,10.57 J6.3
  T03 w0.229: v1(28.88,12.58) 30.03,13.73 38.77,13.73 50.22,2.28 237.77,2.28 238.67,3.17 v1(238.67,3.69)
  BOTTOM w0.229: J1.5 R6.1 28.88,13.77 D3.2 v1(28.88,12.58)
FAN2_DIR#: length 39.3
  TOP w0.229: v1(60.66,20.18) U11.5
  T03 w0.229: v1(60.66,20.18) 60.66,16.52 64.47,12.71 v1(78.84,12.71)
  BOTTOM w0.229: J2.6 78.84,22.32 78.84,22.32 R82.1 D17.2 v1(78.84,12.71)
FAN2_LED_G: length 128.9
  TOP w0.229: v1(92,19.64) 91.56,20.09 75.98,20.09 71.68,15.78 67.85,15.78 66.31,17.32 66.31,20.02 60.66,25.67 R73.2 ; v1(160.55,6.25) 161.19,6.89 U9.6
  BOTTOM w0.229: C26.1 161.17,6.25 161.17,6.25 v1(160.55,6.25) 159.93,6.25 158.48,7.7 158.48,10.41 155.95,12.94 148.16,12.94 144.4,9.18 97.55,9.18 91.35,15.38 91.35,18.99 v1(92,19.64)
FAN2_LED_Y: length 127.9
  TOP w0.229: v1(93.86,14.59) 93.86,16.62 91.08,19.4 76.27,19.4 71.97,15.1 67.57,15.1 65.63,17.04 65.63,19.73 60.76,24.6 57.11,24.6 56.04,25.67 R72.2 ; v1(160.48,7.19) 160.83,7.54 U9.5
  BOTTOM w0.229: v1(93.86,14.59) 98.59,9.87 144.11,9.87 147.87,13.62 156.23,13.62 159.16,10.69 159.16,7.98 159.96,7.19 v1(160.48,7.19) 161,7.19 161,7.19 C25.1
FAN2_PRSNT_N: length 176.4
  TOP w0.229: J6.9 v1(237.87,12.94)
  T03 w0.229: v1(146.13,3.65) 98.72,3.65 98.65,3.72 v1(98.1,3.72)
  BOTTOM w0.229: v1(98.1,3.72) 98.1,7.23 97.28,8.05 Q4.1 94.67,8.05 89.03,13.69 D5.2 89.03,14.49 89.02,14.49 R11.1 89.02,17.18 89,17.2 J2.2 ; v1(146.13,3.65) 146.88,2.91 231.3,2.91 232.67,4.28 232.67,5.94 234.96,8.23 234.96,11.3 236.6,12.94 v1(237.87,12.94)
FAN2_PWM_CTRL: length 170.5
  TOP w0.381: J6.13 v2(233.87,9.68)
  T03 w0.381: v2(233.87,9.68) 229.92,5.72 224.96,5.72 223.65,4.41 147.19,4.41 146.5,5.1 141.2,5.1 136.44,9.85 86.84,9.85 v2(83.95,12.74)
  BOTTOM w0.381: v2(83.95,12.74) D4.2 83.95,14.54 83.92,14.57 J2.4
FAN2_PWR: length 5.2
  BOTTOM w1.524: 90.91,20.68 91.54,21.31 J2.1
  vias: v1(89.53,17.41) v1(90.3,17.31) v2(80.32,8.54) v2(80.35,7.76)
FAN2_PWR_ON: length 6
  BOTTOM w0.229: R9.1 92.95,6.27 R8.2 91.96,6.27 R10.1 90.99,6.25 C6.1 89.74,6.2 88.86,6.2 87.59,7.46 U2.1
FAN2_TACH_IN: length 176.8
  TOP w0.229: J6.11 v1(235.87,9.68)
  T03 w0.229: v1(235.87,9.68) 235.87,9.08 231.76,4.96 225.28,4.96 223.97,3.65 146.87,3.65 146.18,4.34 140.88,4.34 136.13,9.09 83.71,9.09 81.38,11.42 v1(81.38,12.73)
  BOTTOM w0.229: v1(81.38,12.73) D6.2 R12.1 J2.5
FAN3_DIR#: length 89.3
  TOP w0.229: v1(60.05,20.83) U11.6
  T03 w0.229: v1(60.05,20.83) 62.22,20.83 68.39,14.66 85.32,14.66 86.59,13.39 86.59,13.39 87.36,12.62 129.61,12.62 130.8,13.81 v1(131.32,13.81)
  BOTTOM w0.229: J3.6 131.34,22.32 131.34,22.32 R83.1 131.34,15.47 131.32,15.45 D18.2 v1(131.32,13.81)
FAN3_LED_G: length 75.3
  TOP w0.229: C28.1 171.2,8.27 170,8.27 169.92,8.19 U9.11 167.5,8.19 160.97,14.72 146.98,14.72 144.36,17.33 132.57,17.33 130.23,15 113.68,15 107.01,21.66 R75.2
FAN3_LED_Y: length 76.8
  TOP w0.229: C27.1 170.8,7.71 169.74,7.71 169.58,7.54 U9.10 167.18,7.54 160.69,14.03 146.69,14.03 144.08,16.65 133.13,16.65 130.79,14.31 113.39,14.31 106.02,21.68 R74.2
FAN3_PRSNT_N: length 131.3
  TOP w0.229: v1(229.88,9.46) 229.87,9.46 J6.17 ; v1(120.76,7.38) 133.64,7.38 139.96,13.7 v1(141.53,13.7)
  T03 w0.229: v1(141.53,13.7) 141.83,13.4 150.47,13.4 151.46,14.39 170.81,14.39 172.64,12.56 180.73,12.56 183.17,10.12 206.23,10.12 206.58,9.78 217.88,9.78 218.4,10.3 226.24,10.3 227.59,8.95 229.37,8.95 v1(229.88,9.46)
  BOTTOM w0.229: v1(141.53,13.7) D8.2 141.53,15.43 141.5,15.45 R17.1 141.5,22.32 141.5,22.33 J3.2 ; Q6.1 120.1,8.04 v1(120.76,7.38)
FAN3_PWM_CTRL: length 105.7
  TOP w0.381: J6.21 v2(225.87,12.99)
  T03 w0.381: v2(225.87,12.99) 224.63,11.75 195.47,11.75 194.46,12.76 182.61,12.76 181.36,14.01 173.24,14.01 171.41,15.83 150.86,15.83 150.02,15 145.23,15 144.4,14.16 142.15,14.16 141.74,14.56 v2(137.6,14.56)
  BOTTOM w0.381: J3.4 136.42,21.22 136.42,21.21 136.42,15.49 136.45,15.45 D7.2 137.49,14.68 v2(137.6,14.56)
FAN3_PWR: length 5.2
  BOTTOM w1.524: J3.1 144.04,20.42 144.02,20.4
  vias: v1(142.6,14.95) v1(143.36,14.95) v2(102.5,8.47) v2(103.54,8.52)
FAN3_PWR_ON: length 6
  BOTTOM w0.229: U3.1 110.35,7.97 111.55,6.77 111.55,6.45 111.78,6.22 C9.1 113.44,6.22 R16.1 114.41,6.25 R14.2 115.4,6.24 R15.1
FAN3_TACH_IN: length 111.1
  TOP w0.229: J6.19 v1(227.87,9.63)
  T03 w0.229: v1(227.87,9.63) 226.52,10.98 195.13,10.98 194.27,11.85 182.43,11.85 181.03,13.24 172.92,13.24 171.09,15.07 151.17,15.07 150.34,14.23 v1(145.55,14.23)
  BOTTOM w0.229: J3.5 R18.1 133.88,15.48 133.91,15.45 D9.2 133.91,14.05 134.8,13.17 144.48,13.17 v1(145.55,14.23)
FAN4_DIR#: length 143.4
  TOP w0.229: v1(59.57,21.88) 59.49,21.88 59.09,21.48 U11.7
  T03 w0.229: v1(182.74,14.63) 182.14,15.22 173.99,15.22 172.16,17.05 150.35,17.05 149.51,16.22 145.3,16.22 132.07,16.22 129.16,13.31 87.64,13.31 85.61,15.34 79.44,15.34 79.43,15.35 68.67,15.35 62.14,21.88 v1(59.57,21.88)
  BOTTOM w0.229: J4.6 183.84,17.18 183.84,17.18 R84.1 183.84,15.36 183.87,15.33 D19.2 v1(182.74,14.63)
FAN4_LED_G: length 36.9
  TOP w0.229: R77.2 162.76,24.89 v1(162.77,24.88) ; C30.1 170.59,10.25 v1(170.42,10.07) 169.84,9.49 U9.13 ; U10.1 179.95,6.42 v1(179.36,6.42)
  BOTTOM w0.229: v1(179.36,6.42) 179.36,7.99 177.62,9.73 172.77,9.73 172.42,10.07 v1(170.42,10.07) 167.83,10.07 162.77,15.13 v1(162.77,24.88)
FAN4_LED_Y: length 25.4
  TOP w0.229: C29.1 171.23,9.31 v1(170.62,9.31) 170.15,8.84 U9.12 ; R76.2 161.01,25.25 161.02,25.25 v1(161.02,24.93)
  BOTTOM w0.229: v1(161.02,24.93) 162.09,23.86 162.09,14.84 167.62,9.31 v1(170.62,9.31)
FAN4_PRSNT_N: length 78.9
  TOP w0.229: J6.2 245.87,7.83 v1(245.87,7.88)
  T03 w0.229: v1(196.03,12.47) 196.4,12.84 224.64,12.84 225.39,13.58 238.3,13.58 240.43,11.45 240.43,7.72 241.19,6.96 244.95,6.96 v1(245.87,7.88)
  BOTTOM w0.229: J4.2 R23.1 D11.2 194,14.5 v1(196.03,12.47) 198.95,9.55 Q8.1
FAN4_PWM_CTRL: length 72.2
  TOP w0.381: v2(241.88,8.19) J6.6
  T03 w0.381: v2(241.88,8.19) 241.88,12.14 238.46,15.55 190.85,15.55 v2(189.85,14.55)
  BOTTOM w0.381: J4.4 D10.2 v2(189.85,14.55)
FAN4_PWR: length 7.4
  BOTTOM w0.762: v2(187.18,10.73) 187.18,10.55 186.42,9.79 Q7.3
  BOTTOM w1.524: J4.1 v1(196.54,19.78)
FAN4_PWR_ON: length 5.9
  BOTTOM w0.229: U4.1 192.37,8.96 193.58,7.75 C12.1 195.76,7.75 R22.1 195.79,7.77 R20.2 197.72,7.77 R21.1
FAN4_TACH_IN: length 76.5
  TOP w0.229: v1(243.87,7.93) J6.4
  T03 w0.229: v1(187.49,14.63) 188.08,14.03 190.53,14.03 191.3,14.79 238.06,14.79 241.11,11.74 241.11,8 241.47,7.64 243.06,7.64 243.35,7.93 v1(243.87,7.93)
  BOTTOM w0.229: v1(187.49,14.63) D12.2 R24.1 J4.5
FAN5_DIR#: length 202.9
  TOP w0.229: U11.9 v1(53.91,22.13)
  T03 w0.229: v1(236.34,17.74) 234.97,16.37 190.51,16.37 190.05,15.91 174.28,15.91 172.45,17.74 150.07,17.74 149.23,16.9 145.58,16.9 145.58,16.9 131.78,16.9 128.87,14 87.93,14 85.53,16.39 68.62,16.39 62.34,22.67 54.45,22.67 v1(53.91,22.13)
  BOTTOM w0.229: D20.2 236.32,14.65 236.34,14.67 R85.1 236.34,17.18 236.34,17.18 v1(236.34,17.74) J5.6
FAN5_LED_G: length 38.7
  TOP w0.229: U10.4 182.26,8.37 182.44,8.54 v1(183.27,8.54) 183.98,8.54 C33.1 ; v1(183.27,7.3) 183.27,6.77 185.02,5.02 190.94,5.02 207.57,21.66 R79.2
  T03 w0.229: v1(183.27,7.3) v1(183.27,8.54)
FAN5_LED_Y: length 35.2
  TOP w0.229: U10.3 182.26,7.72 182.48,7.93 183.62,7.93 184.18,7.38 C32.1 184.18,6.83 185.3,5.71 190.65,5.71 206.53,21.58 R78.2
FAN5_PRSNT_N: length 50.7
  TOP w0.229: J6.10 237.87,7.72 237.88,7.72 v1(237.88,7.88) 237.29,8.47 227.33,8.47 226.8,9 226.8,13.36 225.88,14.27 v1(218.7,14.27)
  BOTTOM w0.229: Q10.1 218.14,13.95 218.46,14.27 v1(218.7,14.27) ; J5.2 R29.1 D14.2 246.5,13.69 240.7,7.88 v1(237.88,7.88)
FAN5_PWM_CTRL: length 26.1
  TOP w0.381: J6.14 v2(233.87,4.73)
  BOTTOM w0.381: v2(233.87,4.73) 240.11,10.97 240.11,12.33 241.42,13.63 D13.2 J5.4
FAN5_PWR: length 8.2
  BOTTOM w1.524: J5.1 249.04,19.85 249.05,19.84 v1(249.05,18.67) v2(249.05,17.4)
  vias: v2(201.2,14.04) v2(202.27,14.04)
FAN5_PWR_ON: length 5.5
  BOTTOM w0.229: R27.1 213.9,12.19 R26.2 212.91,12.19 R28.1 211.94,12.17 C15.1 210.09,12.17 208.98,13.28 U5.1
FAN5_TACH_IN: length 21.1
  TOP w0.229: J6.12 v1(235.87,7.88)
  BOTTOM w0.229: v1(235.87,7.88) 237.07,9.08 237.07,11.19 238.88,13 D15.2 R30.1 J5.5
FAN_GND: length 220
  TOP w0.381: J6.8 239.87,4.9 v2(240.27,4.51) ; J6.8 239.87,7.66 ; J6.8 239.21,6.31 ; J6.8 240.53,6.31 ; U6.4 70.97,6.82 ; U6.4 71.99,6.39 ; U6.4 v2(69.34,6.39) ; 130.76,6.31 U8.4 ; U8.4 132.83,6.31 v2(133.05,6.54) ; U8.4 131.78,6.74 ; U7.4 164.98,20.59 v2(165.26,20.86) ; U7.4 163.96,21.02 ; U7.4 162.95,20.59 ; C32.2 185.51,7.35 ; C32.2 185,6.82 ; C32.2 185,8.34 C33.2 185.88,8.37 v2(185.96,8.44) ; v2(180.37,10.98) 181.04,10.32 U10.7 ; v2(166.94,12.27) 167.14,12.08 C22.1 ; 239.21,11.25 J6.7 ; J6.7 v2(239.87,9.57) ; J6.7 239.87,12.6 ; J6.7 240.53,11.25 ; D22.3 v2(54.26,28.32) ; C22.1 167.65,12.61 ; C22.1 167.65,11.54 ; R52.1 154.01,20.86 154.01,20.86 v2(153.68,20.86) ; R52.1 154.45,21.39 ; R52.1 154.45,20.32 ; J6.26 222.54,6.31 ; J6.26 221.88,7.66 ; J6.26 v2(220.66,6.31) ; J6.26 221.88,4.96 ; 137.18,5.55 R56.2 ; R56.2 137.18,6.62 ; R56.2 137.85,6.09 137.9,6.03 137.98,6.03 v2(138.06,5.95) ; 231.21,11.25 J6.15 ; J6.15 231.88,12.6 ; J6.15 232.54,11.25 ; J6.15 v2(231.88,9.61) ; C29.2 v1(172.98,9.18) ; R69.2 v2(65.11,17.16) ; R69.2 64.36,17.69 ; R69.2 64.36,16.62 ; R40.1 61.54,7.14 ; R40.1 v2(60.74,6.61) ; R40.1 61.54,6.07 ; R68.2 64.34,16.5 ; R68.2 64.34,15.43 ; R68.2 v2(65.07,15.96) ; 61.49,4.88 R38.1 ; R38.1 61.49,5.95 ; R38.1 v2(60.73,5.41) ; 64.34,17.82 R80.2 ; R80.2 64.84,18.35 ; R80.2 64.34,18.89 ; D23.3 v2(106.76,28.32) ; 154.43,17.93 R49.1 ; R49.1 154.43,19 ; R49.1 v2(153.68,18.47) ; 49.05,17.58 C34.2 ; C34.2 49.56,18.11 ; C34.2 v2(49.56,16.81) ; v1(172.91,7.33) 172.73,7.15 C27.2 ; U9.7 161.82,6.24 161.44,5.86 v1(161.44,5.51) ; U9.7 162.67,5.81 ; U9.7 163.68,6.24 ; U10.7 181.26,10.75 ; U10.7 182.28,10.32 ; R58.2 137.9,4.44 v2(137.9,4.84) 137.85,4.89 R57.2 ; U11.8 v2(56.86,22.13) ; R57.2 137.16,4.35 ; R57.2 137.16,5.42 ; R59.2 123.06,6.21 ; R59.2 123.06,5.14 ; R59.2 v2(122.13,5.68) ; v2(153.65,19.66) R50.1 ; R50.1 154.4,19.13 ; R50.1 154.4,20.2 ; C28.2 v1(172.98,8.11) ; R37.1 v2(60.71,4.22) ; R37.1 61.52,3.68 ; R37.1 61.52,4.75 ; R63.2 v2(217.89,7.76) ; C30.2 v1(172.98,10.25) ; D24.3 159.26,28.07 v2(159.24,28.05) ; D21.3 v2(1.76,28.25)
  BOTTOM w0.381: 28.07,11.36 D3.1 ; D3.1 29.7,11.36 ; D3.1 v1(28.88,10.37) ; C31.1 176.65,6.25 ; C31.1 175.94,6.99 ; C31.1 176.42,5.78 v2(176.54,5.78) ; C31.1 175.94,5.52 ; D11.1 193.21,12.2 192.92,11.91 v1(192.92,11.31) ; D11.1 194.81,12.2 ; D11.1 194,13.12 ; D11.1 194,11.29 ; 78.03,11.41 D17.1 ; D17.1 78.84,10.67 v1(78.65,10.47) ; D17.1 79.65,11.41 ; v2(98.43,8.04) C4.2 ; D5.1 v1(87.99,11.39) ; D5.1 89.84,11.39 ; D5.1 89.03,12.3 ; D5.1 89.03,10.47 ; C23.2 v2(164.55,9.08) ; D18.1 v1(132.41,12.35) ; D13.1 242.24,11.34 242.25,11.35 v1(242.85,11.35) ; D13.1 241.42,10.42 ; D13.1 241.42,12.25 ; v2(76.51,4.77) 77.36,3.92 C10.2 ; v2(236.91,12.38) 236.32,11.78 D20.1 ; C21.2 128.48,5.1 v2(128.46,5.12) ; C21.2 128.48,3.59 ; C21.2 129.19,4.33 ; 88.88,7.62 C6.2 ; C6.2 90.71,7.62 ; C6.2 v2(89.79,8.57) ; C1.2 v2(23.53,3.46) ; C1.2 23.53,5.85 ; C1.2 22.56,4.68 ; D1.1 v1(31.45,10.4) ; D1.1 32.27,11.34 ; D1.1 30.64,11.34 ; v2(158.5,18.3) 159.04,18.83 C20.2 ; R22.2 195.79,9 v2(196.17,9.38) ; 207.96,11.38 U5.2 ; U5.2 209.84,10.5 v2(209.84,10.35) 209.13,9.64 C11.2 ; U5.2 208.95,10.41 ; U5.2 209.94,11.38 ; 87.57,4.6 U2.2 ; U2.2 v2(88.69,5.56) ; U2.2 86.58,5.56 ; v2(193.53,9.59) 194,9.12 C12.2 ; 26.34,10.47 D16.1 ; D16.1 v1(27.24,11.39) ; D16.1 26.34,12.3 ; D16.1 25.52,11.39 ; 185.57,12.23 D12.1 ; D12.1 186.38,13.14 ; D12.1 187.19,12.23 ; D12.1 v1(186.38,11.29) ; C7.2 v2(180.37,10.98) ; C7.2 181.85,11.95 ; C7.2 183.02,10.98 ; D2.1 v1(36.52,10.45) ; C12.2 195.48,9.12 ; C12.2 194.57,9.96 ; C3.2 v2(33.81,9.66) ; C3.2 34.72,8.71 ; C3.2 32.9,8.71 ; C15.2 210.75,14.38 ; C15.2 211.66,13.54 ; C15.2 211.25,14.04 v2(211.97,14.04) R28.2 ; R16.2 113.46,7.71 v2(113.55,7.79) ; C2.2 v2(27.47,3.67) ; C19.2 v2(68.08,4.43) ; C19.2 67.18,5.17 ; C19.2 67.18,3.7 ; U1.2 v2(31.58,5.62) ; U1.2 30.59,6.65 ; U1.2 32.58,6.65 ; C20.2 159.42,19.57 ; C20.2 159.42,18.09 ; D14.1 246.5,12.3 ; D14.1 246.5,10.74 v1(246.82,10.42) ; D14.1 245.69,11.39 ; D14.1 247.31,11.39 ; U3.2 v2(110.32,4.96) ; v2(221.75,8.91) 222.05,9.22 C18.2 222.21,11.41 C17.2 ; 192.34,6.1 U4.2 ; U4.2 v2(191.27,7.06) ; U4.2 193.33,7.06 ; v2(203.13,9.59) C13.2 ; R4.2 v2(35.03,8.93) ; v1(188.81,11.21) 188.92,11.33 D10.1 ; 209.13,8.87 C11.2 ; C11.2 209.84,9.61 ; C26.2 v2(164.6,6.25) ; C8.2 v2(101.38,8.14) ; D19.1 183.87,13.14 ; D19.1 183.87,11.81 v1(184.39,11.29) 183.7,10.6 C5.2 ; D19.1 184.68,12.23 ; D19.1 183.05,12.23 ; 80.57,11.41 D6.1 ; D6.1 v1(81.38,10.47) ; D6.1 82.19,11.41 ; v2(237.68,9.43) 238.88,10.64 D15.1 ; D10.1 189.73,12.15 ; D10.1 188.92,13.07 ; D10.1 188.11,12.15 ; 83.14,11.36 D4.1 ; D4.1 v1(83.95,10.42) ; D4.1 84.77,11.36 ; C24.2 v2(164.58,8.14) ; D7.1 v1(135.62,12.28) ; D9.1 v1(134.78,12.35) ; R10.2 v2(91.01,7.83) ; v2(164.45,7) 164.26,7.19 C25.2 ; D8.1 v1(140.69,12.33) ; C9.2 v2(112.25,8.52) ; C14.2 v2(77.6,7.86)
  BOTTOM w1.016: J2.3 v2(86.46,20.61) ; J1.3 v2(33.96,20.36)
  BOTTOM w1.524: J4.3 v2(191.46,20.21) ; J5.3 v2(243.96,20.19) ; J3.3 v2(138.96,20.08)
  vias: v1(68.51,17.89) v1(145.58,17.79) v1(215.53,10.3) v1(270.82,14.67) v1(270.87,13.42) v2(0.85,2.42) v2(0.85,0.85) v2(0.87,26.98) v2(0.87,25.71) v2(0.87,24.44) v2(0.87,23.17) v2(0.87,21.9) v2(0.87,20.63) v2(0.87,19.36) v2(0.87,18.09) v2(0.87,16.82) v2(0.87,15.55) v2(0.87,14.28) v2(0.87,13.01) v2(0.87,11.74) v2(0.87,10.47) v2(0.87,9.2) v2(0.87,7.93) v2(0.87,6.66) v2(0.87,5.39) v2(0.87,4.12) v2(2.8,0.8) v2(4.07,0.8) v2(5.34,0.8) v2(6.61,0.8) v2(6.84,29.96) v2(7.88,0.8) v2(8.31,29.96) v2(9.15,0.8) v2(9.58,29.96) v2(10.42,0.8) v2(10.85,29.96) v2(11.69,0.8) v2(12.12,29.96) v2(12.96,0.8) v2(13.39,29.96) v2(14.23,0.8) v2(14.94,28.86) v2(15.25,26.98) v2(15.5,0.8) v2(15.55,18.78) v2(16.44,17.49) v2(16.77,0.8) v2(18.04,0.8) v2(19.11,17.46) v2(19.31,0.8) v2(20.2,19.14) v2(20.58,0.8) v2(21.85,0.8) v2(23.12,0.8) v2(24.39,0.8) v2(25.66,0.8) v2(26.93,0.8) v2(28.2,0.8) v2(29.47,0.8) v2(30.74,0.8) v2(32.01,0.8) v2(32.8,11.69) v2(33.28,0.8) v2(34.55,0.8) v2(34.88,11.72) v2(35.82,0.8) v2(37.09,0.8) v2(38.36,0.8) v2(39.63,0.8) v2(40.83,17.54) v2(41.05,0.8) v2(42.32,0.8) v2(43.59,0.8) v2(44.1,17.51) v2(44.86,27.47) v2(44.86,26.2) v2(44.86,24.93) v2(44.86,23.66) v2(44.86,22.39) v2(44.86,21.12) v2(44.89,19.19) v2(44.86,0.8) v2(45.25,29.07) v2(46.13,0.8) v2(46.54,29.83) v2(47.4,0.8) v2(48.29,30.01) v2(48.67,0.8) v2(49.94,0.8) v2(50.12,29.98) v2(51.21,0.8) v2(51.93,29.96) v2(52.48,0.8) v2(53.75,0.8) v2(55.02,0.8) v2(56.29,0.8) v2(57.56,0.8) v2(58.83,0.8) v2(59.55,30.01) v2(60.1,0.8) v2(61.09,29.98) v2(61.37,0.8) v2(62.64,0.8) v2(62.87,29.98) v2(63.91,0.8) v2(64.98,30.01) v2(65.18,0.8) v2(66.45,0.8) v2(66.76,29.68) v2(67.72,0.8) v2(67.88,28.31) v2(67.9,26.73) v2(67.85,25.11) v2(67.9,23.12) v2(67.9,21.63) v2(67.9,19.92) v2(68.99,0.8) v2(70.26,0.8) v2(71.53,0.8) v2(71.89,17.64) v2(72.75,19.39) v2(72.8,0.8) v2(74.07,0.8) v2(75.34,0.8) v2(76.61,0.8) v2(77.88,0.8) v2(79.31,0.82) v2(80.58,0.82) v2(81.85,0.82) v2(83.12,0.82) v2(84.39,0.82) v2(85.66,0.82) v2(86.93,0.82) v2(88.2,0.82) v2(89.47,0.82) v2(90.74,0.82) v2(92.01,0.82) v2(93.28,0.82) v2(94.55,0.82) v2(94.72,17.08) v2(95.79,17.21) v2(95.82,0.82) v2(97.09,0.82) v2(97.16,18.12) v2(97.34,19.75) v2(97.42,27.67) v2(97.42,26.4) v2(97.42,25.13) v2(97.42,23.86) v2(97.42,22.59) v2(97.42,21.32) v2(98.36,0.82) v2(99.04,29.88) v2(99.63,0.82) v2(100.31,29.88) v2(100.9,0.82) v2(101.58,29.88) v2(102.17,0.82) v2(102.85,29.88) v2(103.44,0.82) v2(104.12,29.88) v2(104.71,0.82) v2(105.98,0.82) v2(107.25,0.82) v2(108.52,0.82) v2(109.79,0.82) v2(111.06,0.82) v2(112,29.88) v2(112.33,0.82) v2(113.27,29.88) v2(113.6,0.82) v2(114.54,29.88) v2(114.87,0.82) v2(115.81,29.88) v2(116.14,0.82) v2(117.08,29.88) v2(117.53,0.8) v2(118.8,0.8) v2(120.07,0.8) v2(120.38,27.29) v2(120.38,26.02) v2(120.51,19.01) v2(120.96,17.82) v2(121.34,0.8) v2(122.16,17.13) v2(122.61,0.8) v2(123.88,0.8) v2(124.06,17.38) v2(125.05,18.63) v2(125.15,0.8) v2(126.42,0.8) v2(127.69,0.8) v2(128.96,0.8) v2(130.23,0.8) v2(131.5,0.8) v2(132.77,0.8) v2(134.04,0.8) v2(135.31,0.8) v2(136.58,0.8) v2(137.21,18.12) v2(137.85,0.8) v2(138.99,18.16) v2(139.12,0.8) v2(140.39,0.8) v2(141.66,0.8) v2(142.93,0.8) v2(144.2,0.8) v2(145.47,0.8) v2(146.74,0.8) v2(148.01,0.8) v2(149.28,0.8) v2(149.61,18.07) v2(149.92,27.67) v2(149.92,26.4) v2(149.92,25.13) v2(149.92,23.86) v2(149.92,22.59) v2(149.92,21.32) v2(149.87,19.54) v2(150.55,0.8) v2(150.99,29.63) v2(151.82,0.8) v2(152.2,29.96) v2(153.09,0.8) v2(153.47,29.96) v2(154.36,0.8) v2(154.74,29.96) v2(155.79,0.8) v2(156.01,29.96) v2(157.06,0.8) v2(158.33,0.8) v2(159.6,0.8) v2(160.87,0.8) v2(162.14,0.8) v2(163.41,0.8) v2(164.52,29.91) v2(164.68,0.8) v2(165.79,29.91) v2(165.95,0.8) v2(167.06,29.91) v2(167.22,0.8) v2(168.33,29.91) v2(168.49,0.8) v2(169.6,29.91) v2(169.76,0.8) v2(171.03,0.8) v2(172.3,0.8) v2(172.83,27.98) v2(172.83,26.71) v2(172.83,25.44) v2(172.83,24.17) v2(172.83,22.9) v2(172.83,21.63) v2(172.83,20.43) v2(172.96,19.14) v2(173.57,17.69) v2(173.57,0.8) v2(174.84,0.8) v2(176.11,0.8) v2(177.22,17.82) v2(177.38,0.8) v2(177.53,18.65) v2(177.66,19.75) v2(178.65,0.8) v2(179.92,0.8) v2(181.19,0.8) v2(182.46,0.8) v2(183.73,0.8) v2(185,0.8) v2(186.27,0.8) v2(187.54,0.8) v2(188.81,0.8) v2(189.69,17.99) v2(190.08,0.8) v2(191.35,0.8) v2(191.47,17.92) v2(192.62,0.8) v2(193.32,19.75) v2(194.06,11.03) v2(194.32,0.8) v2(195.59,0.8) v2(196.86,0.8) v2(198.13,0.8) v2(198.31,17.64) v2(199.4,0.8) v2(199.47,17.1) v2(200.67,0.8) v2(201.33,17.31) v2(201.94,0.8) v2(202.37,27.06) v2(202.37,25.79) v2(202.37,24.52) v2(202.37,23.25) v2(202.37,21.98) v2(202.37,20.71) v2(202.45,18.63) v2(203.21,0.8) v2(203.51,29.52) v2(204.48,0.8) v2(204.83,29.96) v2(205.75,0.8) v2(206.1,29.96) v2(207.02,0.8) v2(207.37,29.96) v2(208.29,0.8) v2(208.64,29.96) v2(209.56,0.8) v2(210.52,29.96) v2(210.83,0.8) v2(212.1,0.8) v2(213.37,0.8) v2(214.64,0.8) v2(215.91,0.8) v2(216.75,29.83) v2(217.18,0.8) v2(218.02,29.83) v2(218.45,0.8) v2(219.29,29.83) v2(219.72,0.8) v2(220.56,29.83) v2(220.99,0.8) v2(221.83,29.83) v2(222.26,0.8) v2(223.53,0.8) v2(224.8,0.8) v2(225.23,19.72) v2(225.43,28.08) v2(225.43,26.81) v2(225.43,25.54) v2(225.43,24.27) v2(225.43,23) v2(225.43,21.73) v2(225.84,17.89) v2(226.07,0.8) v2(227.34,0.8) v2(227.97,17.05) v2(228.61,0.8) v2(229.85,18.09) v2(229.88,0.8) v2(231.15,0.8) v2(232.62,0.8) v2(233.89,0.8) v2(235.54,18.76) v2(236.43,0.8) v2(237.7,0.8) v2(238.97,0.8) v2(240.24,0.8) v2(241.51,0.8) v2(242.12,17.87) v2(242.78,0.8) v2(244.05,0.8) v2(245.06,16.55) v2(245.32,0.8) v2(245.61,19.2) v2(246.59,0.8) v2(247.86,0.8) v2(249.13,0.8) v2(250.4,0.8) v2(250.53,18.17) v2(251.62,17.21) v2(251.67,0.8) v2(252.94,0.8) v2(254.01,17.41) v2(254.21,0.8) v2(254.82,18.83) v2(254.92,27.06) v2(254.92,25.79) v2(254.92,24.52) v2(254.92,23.25) v2(254.92,21.98) v2(254.92,20.71) v2(255.05,28.79) v2(255.48,0.8) v2(256.55,29.91) v2(256.75,0.8) v2(257.82,29.98) v2(258.02,0.8) v2(259.09,29.98) v2(259.29,0.8) v2(260.36,29.98) v2(260.56,0.8) v2(261.63,29.98) v2(261.83,0.8) v2(262.9,29.98) v2(263.1,0.8) v2(264.17,29.98) v2(264.37,0.8) v2(265.44,29.98) v2(265.64,0.8) v2(266.71,29.98) v2(266.91,0.8) v2(267.98,29.98) v2(268.18,0.8) v2(269.45,30.01) v2(269.45,0.8) v2(270.85,29.96) v2(270.87,12.15) v2(271.41,0.82) v2(272.17,29.78) v2(272.17,28.51) v2(272.17,27.24) v2(272.17,25.97) v2(272.17,24.7) v2(272.17,23.43) v2(272.17,22.16) v2(272.17,20.89) v2(272.17,19.62) v2(272.17,18.35) v2(272.17,17.08) v2(272.17,15.81) v2(272.17,14.54) v2(272.17,13.27) v2(272.17,12) v2(272.17,10.73) v2(272.17,9.46) v2(272.17,8.19) v2(272.17,6.92) v2(272.17,5.65) v2(272.17,3.9) v2(272.19,2.3)
FAN_P3V3: length 67.8
  TOP w0.381: v2(169.2,12.08) C22.2 168.46,11.48 168.5,11.43 U9.14 ; R65.1 62.12,15.87 62.66,15.87 v2(62.76,15.97) ; U9.2 161.65,9.49 161.48,9.66 v2(161.42,9.66) ; R31.2 v2(73.97,7.86) ; U11.16 C34.1 v2(50.38,16.81) ; U10.2 v2(182.51,7.07) ; v2(127.67,5.14) 126.89,4.36 U8.8 ; R54.1 134.87,4.79 v2(135.59,4.79) ; U7.8 160.87,18.64 v2(161.07,18.83) ; R42.1 224.7,3.19 v2(224.7,3.64) ; R53.1 135.44,6.08 v2(135.57,5.95) ; R34.1 v2(63.12,5.41) ; R32.1 v2(63.1,4.22) ; R67.1 v2(62.71,18.35) ; v2(215.33,7.66) 215.34,7.65 215.91,7.65 216.02,7.76 R62.1 ; R46.1 156.52,20.86 v2(156.22,21.16) ; R45.1 v2(156.1,19.66) ; R55.1 134.82,3.67 135.42,3.06 137.79,3.06 138.87,4.14 138.87,4.16 138.92,4.21 v2(138.92,4.81) ; J6.25 221.88,10.57 220.92,9.61 v2(220.45,9.61) ; R60.1 v2(232.93,3.79) ; v2(65.59,4.18) 65.85,4.43 66.82,4.43 U6.8 ; R66.1 62.1,17.1 62.75,17.1 v2(62.81,17.16) ; R44.1 v2(156.18,18.47) ; R43.2 v2(167.82,21.3) ; v2(174.12,5.83) 174.71,6.42 U10.14 ; R35.1 v2(63.1,6.61) ; R64.1 v2(49.53,18.76) ; R61.1 v2(230.44,3.74) ; R41.1 v2(226.86,3.72)
  BOTTOM w0.381: C21.1 v2(127.67,5.14) ; R6.2 v1(30.44,16.65) ; v1(247.31,17.49) R29.2 ; v2(197.16,9.23) 196.74,8.8 R20.1 ; R30.2 v1(239.69,17.42) ; C19.1 65.87,4.43 65.62,4.18 v2(65.59,4.18) ; Q6.2 v2(118.04,6.06) ; C17.1 220.84,11.67 C18.1 221.24,10.4 v2(220.45,9.61) ; R85.2 v1(237.15,17.43) ; R8.1 v2(91.96,7.83) ; Q8.2 v2(200.87,7.56) ; Q10.2 v2(217.58,10.35) ; C20.1 v2(161.07,18.83) ; R2.1 v2(35.98,8.93) ; R24.2 v1(187.19,17.42) ; R12.2 v1(82.19,15.86) ; R84.2 v1(184.65,17.43) ; v1(89.84,15.89) R11.2 ; R83.2 v1(132.15,18.09) ; Q2.2 v2(41.24,6.16) ; v2(174.12,5.83) 174.55,6.25 C31.2 ; R26.1 v2(212.92,14.04) ; R5.2 v1(34.96,16.35) ; Q4.2 v2(97.22,5.07) ; R81.2 v1(27.89,16.65) ; R18.2 v2(134.69,17.88) ; R23.2 v1(194.81,17.46) ; R17.2 v2(140.69,17.98) ; R14.1 v2(114.41,7.81) ; R82.2 v1(79.65,15.86)
FAN_P12V:
  vias: v2(25.05,3.21) v2(25.84,3.52) v2(26.58,3.24) v2(77.2,6.31) v2(77.17,5.47) v2(77.73,7.02) v2(99.11,5.34) v2(100.13,5.29) v2(179.99,9.46) v2(180.01,8.44) v2(206.77,10.32) v2(207.73,10.3) v2(260.71,8.87) v2(260.81,7.71) v2(262.01,8.9) v2(262.03,7.66) v2(263.13,8.87) v2(263.2,7.68) v2(264.24,8.84) v2(264.35,7.63) v2(265.44,7.6) v2(265.46,8.84)
I2C0_HWM_SCL: length 207.4
  TOP w0.229: v1(74.68,4.43) 74.57,4.43 73.98,5.02 R39.1 ; R41.2 226.04,3.48 225.87,3.65 J6.22 225.87,7.94 v1(225.89,7.96) ; U8.6 v1(124.84,5.66) ; v1(54.29,18.88) U11.14 ; v1(171.2,11.88) 171.2,12.4 171.3,12.51 171.3,15.01 166.97,19.34 R51.1
  T03 w0.229: v1(142.48,8.42) 146.77,12.71 150.75,12.71 151.29,13.25 151.74,13.7 170.2,13.7 171.23,12.67 171.23,11.91 v1(171.2,11.88) 171.97,11.88 171.98,11.87 176.16,11.87 179.49,8.53 179.49,8.22 181.17,6.55 181.18,6.55 181.86,5.86 217.67,5.86 221.42,9.61 224.24,9.61 v1(225.89,7.96)
  BOTTOM w0.229: v1(142.48,8.42) 127.59,8.42 v1(124.84,5.66) 121.85,2.68 77.25,2.68 75.5,4.43 v1(74.68,4.43) 73.24,4.43 58.79,18.88 v1(54.29,18.88)
I2C0_HWM_SDA: length 202.4
  TOP w0.229: R48.1 166.97,18.35 170.43,14.89 v1(170.43,12.5) ; v1(53.84,18.23) U11.15 ; v1(74.61,3.62) 74.23,3.62 73.98,3.86 R36.1 ; v1(223.87,8.1) J6.24 223.87,3.84 223.6,3.57 223.6,2.96 R42.2 ; v1(127.39,6.31) U8.5
  T03 w0.229: v1(223.87,8.1) 220.94,5.17 181.41,5.17 178.73,7.85 178.73,8.02 175.57,11.19 170.98,11.19 170.43,11.74 v1(170.43,12.5) 169.92,13.01 152.03,13.01 151.04,12.02 147.28,12.02 v1(143.8,8.54)
  BOTTOM w0.229: v1(53.84,18.23) 54.3,17.76 58.93,17.76 73.08,3.62 v1(74.61,3.62) 75.34,3.62 76.96,1.99 122.14,1.99 122.21,2.07 122.26,2.07 126.5,6.31 v1(127.39,6.31) 128.81,7.73 142.98,7.73 v1(143.8,8.54)
LED_FAN_CLR_N: length 65.5
  TOP w0.229: J6.23 223.87,10.57 223.23,9.92 222.01,9.92 220.66,8.57 R63.1 R62.2 215.5,8.57 211.27,4.34 173.96,4.34 173.54,4.76 173.54,6.31 ; U9.9 170.65,6.89 171.23,6.31 173.54,6.31 ; U10.9 174.17,9.67 173.54,9.04 173.54,6.31
LED_FAN_SCL: length 74.1
  TOP w0.229: U9.8 168.57,6.17 v1(169.77,6.17) ; J6.16 v1(231.88,4.46) 231.88,3.72 232.11,3.48 R60.2 ; U10.8 175.5,10.4 176.56,10.4 178.21,8.75 v1(178.21,7.81)
  BOTTOM w0.229: v1(231.88,4.46) 231.14,5.19 179.61,5.19 178.21,6.59 v1(178.21,7.81) 174.33,7.81 172.69,6.17 v1(169.77,6.17)
LED_FAN_SDA: length 76.2
  TOP w0.229: J6.18 229.87,4.55 v1(229.62,4.3) R61.2 ; v1(161.07,10.35) 161.59,10.35 162.46,10.35 U9.1
  BOTTOM w0.229: v1(161.07,10.35) 164.55,10.35 170.59,4.3 v1(229.62,4.3)
TEMP_ALERT: length 174
  TOP w0.229: J6.20 227.87,6.99 227.3,7.57 227.26,7.57 224.9,9.93 224.9,12.09 223.46,13.52 v1(222.54,13.52) ; v1(74.96,6.05) 74.94,6.02 R33.2 ; R47.2 167.73,20.35 v1(172.2,15.89)
  T03 w0.229: v1(74.96,6.05) 74.96,7.86 81.03,13.93 85.08,13.93 87.07,11.94 130.18,11.94 133.77,15.53 149.8,15.53 150.64,16.37 171.72,16.37 v1(172.2,15.89) 173.55,14.54 181.59,14.54 182.79,13.34 195.93,13.34 196.11,13.52 v1(222.54,13.52)
N02942: length 4.2
  BOTTOM w0.229: U1.3 R1.2 27.97,7.6 26.96,8.62 Q1.1
N03390: length 2
  BOTTOM w0.229: Q2.3 38.14,8.15 38.14,8.15 R3.2
N11321: length 3.7
  BOTTOM w0.229: U2.3 R7.2 82.8,6.51 82.33,6.04 Q3.1
N11737: length 2
  BOTTOM w0.229: R9.2 94.12,7.06 94.12,7.06 Q4.3
N13765: length 3.5
  BOTTOM w0.229: U3.3 R13.2 106.5,7.02 105.48,8.04 Q5.1
N14181: length 1.4
  BOTTOM w0.229: Q6.3 116.01,7.05 116,7.04 R15.2
N14871: length 2
  BOTTOM w0.229: R21.2 198.89,8.56 198.9,8.55 Q8.3
N17617712: length 3.6
  BOTTOM w0.229: U4.3 R19.2 187.59,8.01 Q7.1
N32077972: length 5.4
  TOP w0.229: U6.6 65.54,5.74 65.21,5.41 R34.2 64.72,5.78 64.49,6 62.87,6 62.3,5.44 R38.2
N32077983: length 5.4
  TOP w0.229: U6.7 65.56,5.09 64.72,4.24 R32.2 64.58,4.36 64.58,4.54 64.37,4.75 62.86,4.75 R37.2
N32078033: length 5.2
  TOP w0.229: U6.5 65.41,6.39 65.19,6.61 R35.2 64.69,6.89 64.39,7.2 62.92,7.2 62.35,6.63 R40.2
N32081443: length 3.3
  TOP w0.229: U6.3 72.36,5.74 72.65,6.02 R33.1 73.15,6.99 R31.1
N32081820: length 5.5
  TOP w0.229: 157.73,18.49 157.93,18.49 158.73,19.29 U7.7 ; 157.73,18.49 157.73,18.74 157.45,19.02 155.77,19.02 155.24,18.49 R49.2 ; 157.73,18.49 R44.2
N32081822: length 5.4
  TOP w0.229: U7.6 158.5,19.94 158.23,19.66 R45.2 157.73,19.97 157.5,20.2 155.73,20.2 155.22,19.69 R50.2
N32081881: length 6
  TOP w0.229: U7.5 158.48,20.59 158.2,20.86 R46.2 157.71,21.38 157.41,21.68 155.57,21.68 155.27,21.38 R52.2
N32081935: length 2.2
  TOP w0.229: R51.2 165.05,19.37 164.97,19.29 U7.2
N32081937: length 2.3
  TOP w0.229: R48.2 165.22,18.38 164.97,18.64 U7.1
N32081960: length 3.3
  TOP w0.229: R43.1 166.15,20.36 R47.1 165.51,20.35 165.09,19.94 U7.3
N48201953: length 3.6
  BOTTOM w0.229: U5.3 R25.2 205,12.33 204.01,13.32 Q9.1
N48202027: length 1.4
  BOTTOM w0.229: R27.2 214.47,12.98 214.49,12.96 Q10.3
N48243003: length 2.4
  TOP w0.229: U6.1 72.29,4.44 72.67,4.05 R36.2
N48243020: length 2.2
  TOP w0.229: R39.2 72.67,5.04 72.63,5.09 U6.2
N48490379: length 3.7
  TOP w0.229: R71.1 5.57,28.26 5.26,28.56 D21.2
N48490381: length 3.3
  TOP w0.229: R70.1 4.42,28 D21.1
N48490814: length 2.4
  TOP w0.229: R72.1 D22.1
N48490816: length 3.1
  TOP w0.229: D22.2 R73.1
N48491189: length 4.1
  TOP w0.229: R74.1 106.02,26.37 108.51,28.86 D23.1
N48491191: length 5.4
  TOP w0.229: D23.2 110.26,28.56 110.06,28.36 110.04,28.36 107.53,25.85 R75.1
N48491244: length 2.2
  TOP w0.229: R76.1 D24.1
N48491268: length 2.9
  TOP w0.229: D24.2 R77.1
N48491368: length 9.1
  TOP w0.229: R78.1 206.53,24.93 209.93,28.33 212.93,28.33 D25.1
N48491396: length 10.7
  TOP w0.229: R79.1 207.57,24.91 210.38,27.72 214.42,27.72 215.26,28.56 D25.2
N48524136: length 2.6
  TOP w0.229: U8.7 124.51,5.01 123.87,5.65 R59.1
N48524194: length 5.4
  TOP w0.229: 134,3.72 133.36,4.36 U8.1 ; 134,3.72 R55.2 ; 134,3.72 134,3.88 134.34,4.22 135.85,4.22 136.34,3.72 R58.1
N48524219: length 5.2
  TOP w0.229: U8.2 133.33,5.01 133.45,4.89 R54.2 133.95,5.18 134.19,5.41 135.82,5.41 135.89,5.34 135.92,5.34 136.34,4.91 R57.1
N48524300: length 5.4
  TOP w0.229: U8.3 133.02,5.66 133.44,6.08 R53.2 133.94,6.27 134.33,6.65 135.83,6.65 136.37,6.11 R56.1
N48567665: length 6.6
  TOP w0.229: R68.1 63.52,15.99 63.02,16.49 61.37,16.49 61.21,16.33 R65.2 60.43,15.97 58.82,17.58 U11.1
N48567697: length 6.4
  TOP w0.229: R69.1 63.55,17.18 63.05,17.68 61.48,17.68 61.23,17.43 R66.2 60.35,17.16 59.29,18.23 U11.2
N48567724: length 6.1
  TOP w0.229: U11.3 59.6,18.88 60.15,18.32 60.63,18.32 60.66,18.35 R67.2 61.16,18.54 61.52,18.91 62.99,18.91 63.52,18.38 R80.1
N48567766: length 2.3
  TOP w0.229: U11.13 R64.2

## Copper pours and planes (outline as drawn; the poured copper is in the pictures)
